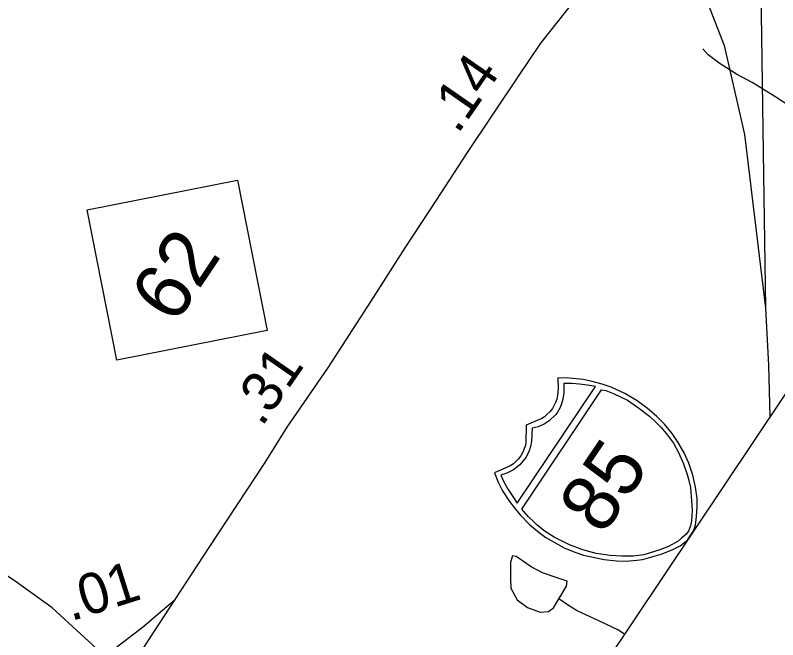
# Model space of a CAD drawing. Extents: x 1715610 to 1720914, y 798298 to 802505.
# Drawn here: x 1716117.1 to 1716168, y 799554.8 to 799596.5 of the extents above; entities that cross this region are included whole.
import ezdxf

# ---------------------------------------------------------------- set-up
doc = ezdxf.new("R2010")
doc.units = 0
doc.layers.add('Default', color=7, linetype='Continuous')
doc.layers.add('Prop DSN Text', color=7, linetype='Continuous')

msp = doc.modelspace()

# ---------------------------------------------------------------- linework, layer by layer
at = {"layer": 'Default'}
msp.add_line((1716162.036, 799561.472), (1716162.393, 799562.005), dxfattribs=at)
for points in [[(1716135.499, 799521.823), (1716119.764, 799533.88), (1716120.919, 799540.982), (1716120.198, 799542.665), (1716116.17, 799545.466), (1716117.998, 799548.07), (1716114.99, 799550.424), (1716119.517, 799551.918), (1716123.32, 799553.423), (1716119.539, 799556.899), (1716117.064, 799558.687), (1716109.933, 799563.384), (1716087.186, 799580.876), (1716088.88, 799582.867), (1716060.136, 799604.726), (1716058.206, 799606.688), (1716067.685, 799613.636), (1716103.505, 799614.09), (1716121.157, 799634.149)], [(1716135.499, 799521.823), (1716119.764, 799533.88), (1716120.919, 799540.982), (1716120.198, 799542.665), (1716116.17, 799545.466), (1716117.998, 799548.07), (1716114.99, 799550.424), (1716119.517, 799551.918), (1716123.32, 799553.423), (1716119.539, 799556.899), (1716117.064, 799558.687), (1716109.933, 799563.384), (1716087.186, 799580.876), (1716088.88, 799582.867), (1716060.136, 799604.726), (1716058.206, 799606.688), (1716067.685, 799613.636), (1716103.505, 799614.09), (1716121.157, 799634.149)], [(1716166.631, 799608.652), (1716166.693, 799607.067), (1716166.929, 799596.605), (1716167.061, 799587.362), (1716167.216, 799576.928)], [(1716161.159, 799601.623), (1716161.768, 799600.56), (1716163.255, 799597.623), (1716164.458, 799594.491), (1716165.812, 799588.557), (1716167.216, 799576.928)], [(1716125.611, 799554.197), (1716127.744, 799557.462), (1716130.016, 799560.935), (1716133.763, 799566.612), (1716135.231, 799568.986), (1716137.963, 799572.926), (1716140.852, 799577.398), (1716143.143, 799580.977), (1716145.264, 799584.224), (1716147.252, 799587.273), (1716150.733, 799592.474), (1716152.195, 799594.659), (1716154.43, 799597.461)], [(1716177.222, 799584.161), (1716175.428, 799585.66), (1716174.703, 799586.527), (1716171.683, 799588.586), (1716167.861, 799591.09), (1716166.338, 799592.024), (1716165.296, 799592.582), (1716164.194, 799593.282), (1716163.391, 799593.879), (1716163.033, 799594.284)], [(1716167.216, 799576.928), (1716167.424, 799573.122), (1716167.527, 799569.675)], [(1716162.393, 799562.005), (1716162.465, 799562.176), (1716162.541, 799562.449), (1716162.599, 799562.779), (1716162.642, 799563.295), (1716162.668, 799563.717), (1716162.667, 799564.224), (1716162.554, 799564.983), (1716162.373, 799565.785), (1716162.091, 799566.576), (1716161.787, 799567.257), (1716161.382, 799567.949), (1716160.986, 799568.566), (1716160.477, 799569.186), (1716159.943, 799569.728), (1716159.341, 799570.224), (1716158.655, 799570.746), (1716157.817, 799571.236), (1716156.9, 799571.647), (1716156.299, 799571.859), (1716155.552, 799572.07), (1716155.052, 799572.17), (1716154.105, 799572.258), (1716153.343, 799572.277), (1716153.36, 799571.553), (1716153.316, 799571.118), (1716153.273, 799570.863), (1716153.177, 799570.635), (1716152.974, 799570.235), (1716152.808, 799570.009), (1716152.615, 799569.825), (1716152.452, 799569.669), (1716152.279, 799569.569), (1716151.227, 799569.116), (1716151.208, 799567.969), (1716151.173, 799567.75), (1716151.094, 799567.554), (1716151.029, 799567.358), (1716150.86, 799567.075), (1716150.713, 799566.871), (1716150.531, 799566.682), (1716150.382, 799566.536), (1716150.163, 799566.408), (1716149.1, 799565.938), (1716149.351, 799565.307), (1716149.635, 799564.738), (1716150.099, 799564.025), (1716150.486, 799563.516), (1716150.817, 799563.117), (1716151.474, 799562.458), (1716152.083, 799561.938), (1716152.541, 799561.612), (1716153.764, 799560.917), (1716154.471, 799560.628), (1716155.06, 799560.423), (1716156.434, 799560.128), (1716157.259, 799560.046), (1716157.882, 799560.032), (1716158.634, 799560.093), (1716159.01, 799560.148), (1716160.26, 799560.484), (1716160.992, 799560.777), (1716161.514, 799561.053), (1716161.727, 799561.205), (1716162.028, 799561.463), (1716162.036, 799561.472)], [(1716153.398, 799557.499), (1716153.571, 799557.753), (1716153.928, 799558.352), (1716153.955, 799558.699), (1716153.222, 799558.937), (1716152.319, 799559.236), (1716151.553, 799559.657), (1716150.977, 799560.048), (1716150.546, 799560.342), (1716150.317, 799560.393), (1716150.182, 799559.963), (1716150.167, 799558.862), (1716150.195, 799558.21), (1716150.621, 799557.447), (1716151.315, 799556.918), (1716152.156, 799556.608), (1716152.714, 799556.653), (1716153.042, 799556.9), (1716153.398, 799557.499)], [(1716153.398, 799557.499), (1716153.571, 799557.753), (1716153.928, 799558.352), (1716153.955, 799558.699), (1716153.222, 799558.937), (1716152.319, 799559.236), (1716151.553, 799559.657), (1716150.977, 799560.048), (1716150.546, 799560.342), (1716150.317, 799560.393), (1716150.182, 799559.963), (1716150.167, 799558.862), (1716150.195, 799558.21), (1716150.621, 799557.447), (1716151.315, 799556.918), (1716152.156, 799556.608), (1716152.714, 799556.653), (1716153.042, 799556.9), (1716153.398, 799557.499)], [(1716123.742, 799554.218), (1716125.655, 799555.67), (1716126.778, 799556.644), (1716127.744, 799557.462)], [(1716157.808, 799555.155), (1716157.358, 799555.428), (1716156.086, 799556.033), (1716154.644, 799556.698), (1716154.046, 799557.06), (1716153.398, 799557.499)]]:
    msp.add_lwpolyline(points, dxfattribs=at)
for points in [[(1716123.854, 799573.464), (1716121.864, 799583.512), (1716131.912, 799585.502), (1716133.902, 799575.455)], [(1716149.54, 799565.784), (1716149.713, 799565.381), (1716149.973, 799564.875), (1716150.278, 799564.406), (1716150.625, 799563.902), (1716155.849, 799571.701), (1716155.322, 799571.79), (1716154.785, 799571.868), (1716154.277, 799571.914), (1716153.751, 799571.907), (1716153.734, 799571.285), (1716153.672, 799570.865), (1716153.589, 799570.55), (1716153.492, 799570.301), (1716153.294, 799569.947), (1716153.184, 799569.802), (1716152.764, 799569.405), (1716152.422, 799569.174), (1716152.019, 799569.007), (1716151.625, 799568.917), (1716151.586, 799568.048), (1716151.523, 799567.694), (1716151.392, 799567.324), (1716151.205, 799566.95), (1716150.791, 799566.457), (1716150.368, 799566.136), (1716149.941, 799565.902)], [(1716156.265, 799571.489), (1716156.541, 799571.425), (1716157.107, 799571.213), (1716157.524, 799571.021), (1716157.999, 799570.793), (1716158.728, 799570.274), (1716159.474, 799569.723), (1716159.882, 799569.347), (1716160.233, 799568.975), (1716160.607, 799568.537), (1716161.079, 799567.92), (1716161.404, 799567.286), (1716161.739, 799566.541), (1716161.983, 799565.816), (1716162.079, 799565.507), (1716162.202, 799564.961), (1716162.28, 799564.066), (1716162.313, 799563.428), (1716162.273, 799562.718), (1716162.215, 799562.382), (1716162.077, 799562.038), (1716161.893, 799561.803), (1716161.612, 799561.555), (1716161.383, 799561.357), (1716160.739, 799561.017), (1716160.163, 799560.779), (1716159.092, 799560.455), (1716158.379, 799560.371), (1716157.605, 799560.364), (1716156.845, 799560.405), (1716155.897, 799560.54), (1716155.013, 799560.78), (1716154.116, 799561.124), (1716153.085, 799561.641), (1716152.496, 799562.016), (1716151.962, 799562.425), (1716151.706, 799562.673), (1716151.39, 799562.987), (1716150.926, 799563.504)]]:
    msp.add_lwpolyline(points, close=True, dxfattribs=at)
at = {"layer": 'Prop DSN Text'}
for points in [[(1715972.317, 799278.019), (1716250.513, 799693.662), (1715888.228, 799936.145), (1715610.032, 799520.501)], [(1715972.317, 799278.019), (1716250.513, 799693.662), (1716295.13, 799663.8), (1716016.934, 799248.156)]]:
    msp.add_lwpolyline(points, close=True, dxfattribs=at)

# ---------------------------------------------------------------- texts
at = {"layer": 'Default'}
for s, height, rotation, p in [('.14', 2.7188, 55.2619, (1716146.652, 799588.522)), ('62', 3.8063, 56.2051, (1716127.74, 799575.761)), ('.31', 2.7188, 55.2619, (1716133.55, 799568.948)), ('85', 3.8063, 56.2051, (1716156.363, 799561.677)), ('.01', 2.7188, 17.5452, (1716120.785, 799555.997))]:
    msp.add_text(s, height=height, rotation=rotation, dxfattribs=at).set_placement(p)

doc.saveas('drawing.dxf')
